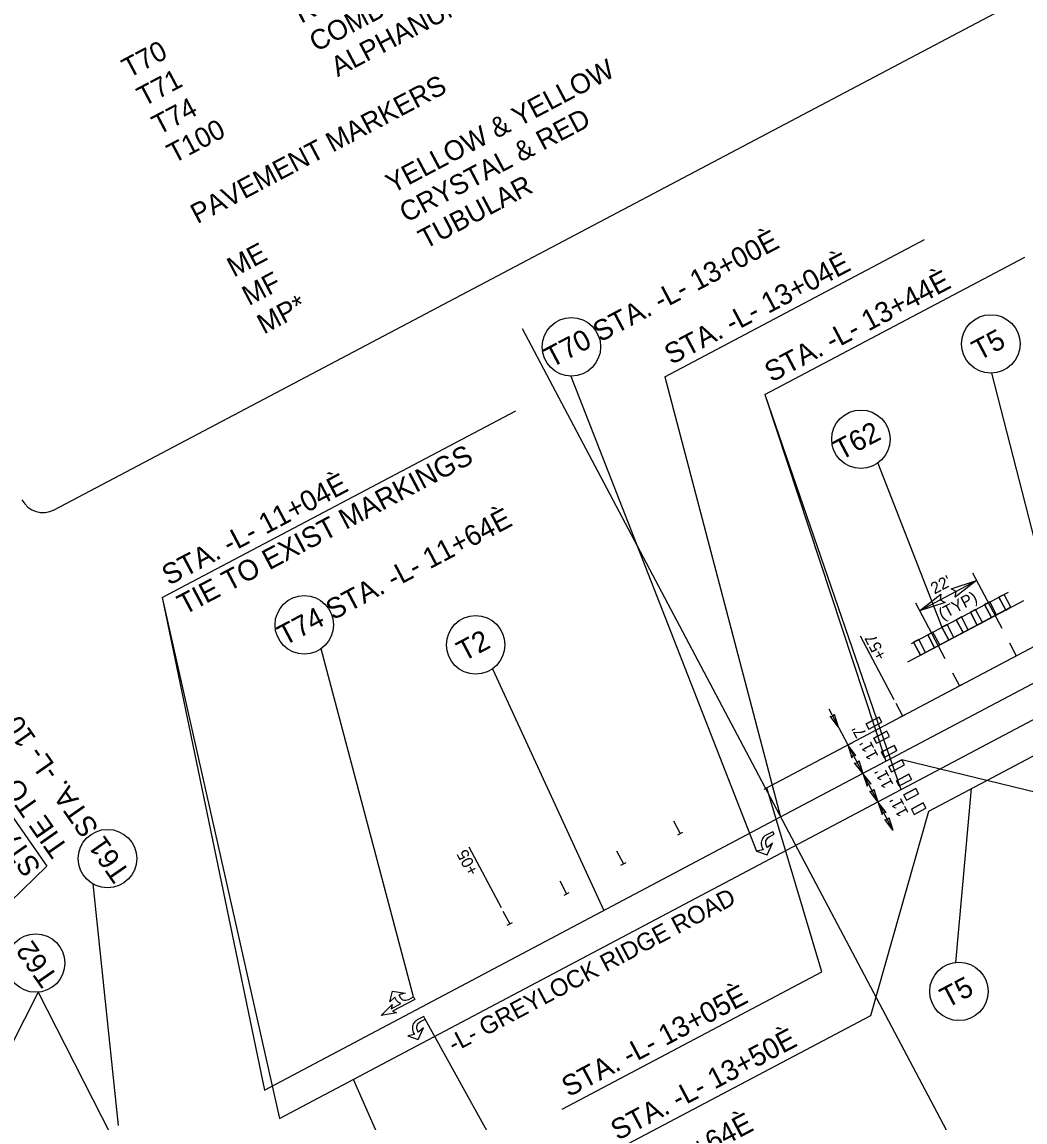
# Model space of a CAD drawing. Extents: x 1487421 to 1489048, y 497792 to 499463.
# Drawn here: x 1487756.3 to 1488099.3, y 498391.7 to 498767.8 of the extents above; entities that cross this region are included whole.
import ezdxf

# ---------------------------------------------------------------- set-up
doc = ezdxf.new("R2010")
doc.units = 0
for name, color, linetype in [('Default', 7, 'Continuous'), ('MARK LEFT TURN ARROW CELL', 7, 'Continuous'), ('MARK STRAIGHT RIGHT ARROW CELL', 7, 'Continuous'), ('Prop Dimension', 7, 'Continuous'), ('Prop Dimension Text', 7, 'Continuous'), ('Prop Horizontal Alignment Direction Label', 7, 'Continuous'), ('Prop Mkg 3ft Min Skp 9ft White', 7, 'Continuous'), ('Prop Mkg Solid Dbl Yel Rpm 80ft', 7, 'Continuous'), ('Prop Mkg Solid White Lane Line', 7, 'Continuous'), ('Scratch_Level_2', 7, 'Continuous'), ('Scratch_Level_3', 7, 'Continuous'), ('Scratch_Level_5', 7, 'Continuous'), ('Scratch_Level_6', 7, 'Continuous'), ('Sheet Title CELL', 7, 'Continuous'), ('Text', 7, 'Continuous')]:
    doc.layers.add(name, color=color, linetype=linetype)

msp = doc.modelspace()

# ---------------------------------------------------------------- linework, layer by layer
at = {"layer": 'MARK LEFT TURN ARROW CELL'}
for points in [[(1488013.55, 498490.11), (1488013.08, 498490.99), (1488010.8, 498489.79), (1488010.39, 498489.54), (1488010.1, 498489.31), (1488009.81, 498489.02), (1488009.6, 498488.71), (1488009.45, 498488.44), (1488009.29, 498488.04), (1488009.22, 498487.71), (1488009.15, 498487.34), (1488009.12, 498486.88), (1488009.16, 498486.54), (1488009.25, 498486.1), (1488009.45, 498485.55), (1488009.82, 498484.84), (1488007.52, 498484.38), (1488011.13, 498483.08), (1488012.98, 498487.07), (1488011.23, 498485.58), (1488010.91, 498486.17), (1488010.76, 498486.51), (1488010.68, 498486.86), (1488010.67, 498487.16), (1488010.69, 498487.56), (1488010.74, 498487.86), (1488010.91, 498488.25), (1488011.16, 498488.59), (1488011.42, 498488.89), (1488011.85, 498489.21)], [(1488013.55, 498490.11), (1488013.08, 498490.99), (1488010.8, 498489.78), (1488010.39, 498489.54), (1488010.1, 498489.31), (1488009.81, 498489.02), (1488009.6, 498488.71), (1488009.45, 498488.44), (1488009.3, 498488.04), (1488009.22, 498487.71), (1488009.15, 498487.34), (1488009.12, 498486.88), (1488009.16, 498486.54), (1488009.25, 498486.1), (1488009.45, 498485.55), (1488009.82, 498484.84), (1488007.53, 498484.38), (1488011.13, 498483.08), (1488012.98, 498487.07), (1488011.23, 498485.58), (1488010.92, 498486.17), (1488010.76, 498486.51), (1488010.68, 498486.86), (1488010.67, 498487.16), (1488010.69, 498487.56), (1488010.74, 498487.86), (1488010.91, 498488.25), (1488011.16, 498488.59), (1488011.42, 498488.89), (1488011.85, 498489.21)], [(1487894.23, 498426.95), (1487893.77, 498427.83), (1487891.48, 498426.63), (1487891.07, 498426.38), (1487890.78, 498426.15), (1487890.49, 498425.86), (1487890.28, 498425.55), (1487890.14, 498425.28), (1487889.98, 498424.88), (1487889.9, 498424.55), (1487889.83, 498424.18), (1487889.81, 498423.72), (1487889.84, 498423.38), (1487889.93, 498422.94), (1487890.13, 498422.39), (1487890.51, 498421.68), (1487888.21, 498421.22), (1487891.82, 498419.92), (1487893.67, 498423.91), (1487891.91, 498422.42), (1487891.6, 498423.01), (1487891.44, 498423.35), (1487891.37, 498423.7), (1487891.35, 498424), (1487891.37, 498424.4), (1487891.43, 498424.7), (1487891.6, 498425.09), (1487891.84, 498425.43), (1487892.11, 498425.73), (1487892.54, 498426.05)], [(1487894.24, 498426.95), (1487893.77, 498427.83), (1487891.48, 498426.62), (1487891.08, 498426.38), (1487890.78, 498426.15), (1487890.49, 498425.86), (1487890.28, 498425.55), (1487890.14, 498425.28), (1487889.98, 498424.88), (1487889.9, 498424.55), (1487889.83, 498424.18), (1487889.81, 498423.72), (1487889.85, 498423.38), (1487889.93, 498422.94), (1487890.13, 498422.39), (1487890.51, 498421.68), (1487888.21, 498421.22), (1487891.82, 498419.92), (1487893.67, 498423.91), (1487891.91, 498422.42), (1487891.6, 498423.01), (1487891.44, 498423.35), (1487891.37, 498423.7), (1487891.35, 498424), (1487891.37, 498424.4), (1487891.43, 498424.7), (1487891.6, 498425.09), (1487891.84, 498425.43), (1487892.11, 498425.73), (1487892.54, 498426.05)]]:
    msp.add_lwpolyline(points, close=True, dxfattribs=at)
at = {"layer": 'MARK STRAIGHT RIGHT ARROW CELL'}
msp.add_lwpolyline([(1487890.69, 498433.66), (1487883.03, 498429.61), (1487884.42, 498429.12), (1487879.18, 498428.15), (1487882.94, 498431.92), (1487882.56, 498430.49), (1487885.9, 498432.26), (1487885.36, 498432.49), (1487885.01, 498432.7), (1487884.66, 498433.03), (1487884.42, 498433.31), (1487884.14, 498433.7), (1487883.78, 498434.44), (1487882.1, 498432.8), (1487883.06, 498436.51), (1487887.4, 498435.78), (1487885.18, 498435.18), (1487885.49, 498434.61), (1487885.69, 498434.28), (1487885.95, 498433.98), (1487886.26, 498433.76), (1487886.59, 498433.56), (1487887.06, 498433.42), (1487887.56, 498433.4), (1487888.05, 498433.47), (1487888.55, 498433.65), (1487890.23, 498434.54)], close=True, dxfattribs=at)
msp.add_lwpolyline([(1487890.69, 498433.66), (1487883.03, 498429.61), (1487884.42, 498429.12), (1487879.18, 498428.15), (1487882.94, 498431.92), (1487882.56, 498430.49), (1487885.9, 498432.26), (1487885.36, 498432.49), (1487885.01, 498432.7), (1487884.66, 498433.03), (1487884.42, 498433.31), (1487884.14, 498433.7), (1487883.78, 498434.44), (1487882.1, 498432.8), (1487883.06, 498436.51), (1487887.4, 498435.78), (1487885.18, 498435.18), (1487885.49, 498434.61), (1487885.69, 498434.28), (1487885.95, 498433.98), (1487886.26, 498433.76), (1487886.59, 498433.56), (1487887.06, 498433.42), (1487887.56, 498433.4), (1487888.05, 498433.47), (1487888.55, 498433.65), (1487890.23, 498434.54)], close=True, dxfattribs=at)
at = {"layer": 'Prop Dimension'}
for p, q in [((1488081.34, 498579.51), (1488091.38, 498560.54)), ((1488063.3, 498566.56), (1488082.74, 498576.86)), ((1488061.89, 498569.22), (1488071.93, 498550.25)), ((1488042.93, 498558.02), (1488054.47, 498536.21)), ((1488032.22, 498533), (1488038.74, 498520.67)), ((1488036.98, 498519.74), (1488040.4, 498521.55)), ((1488038.74, 498520.67), (1488043.89, 498510.95)), ((1488043.89, 498510.95), (1488049.04, 498501.23)), ((1488049.04, 498501.23), (1488054.18, 498491.51)), ((1487909.16, 498485.83), (1487920.13, 498465.1))]:
    msp.add_line(p, q, dxfattribs=at)
for points in [[(1488074.06, 498574.02), (1488082.74, 498576.86), (1488075.49, 498571.21), (1488075.76, 498573.16)], [(1488071.98, 498569.4), (1488063.3, 498566.56), (1488070.55, 498572.21), (1488070.28, 498570.26)], [(1488034.05, 498531.2), (1488035.47, 498526.86), (1488032.64, 498530.48), (1488033.62, 498530.35)], [(1488041.53, 498517.06), (1488038.74, 498520.67), (1488040.15, 498516.3), (1488040.59, 498517.18)], [(1488042.47, 498515.29), (1488043.89, 498510.95), (1488041.07, 498514.57), (1488042.04, 498514.44)], [(1488046.68, 498507.33), (1488043.89, 498510.95), (1488045.3, 498506.58), (1488045.74, 498507.46)], [(1488047.62, 498505.57), (1488049.04, 498501.23), (1488046.21, 498504.85), (1488047.19, 498504.72)], [(1488051.83, 498497.61), (1488049.04, 498501.23), (1488050.45, 498496.85), (1488050.88, 498497.74)], [(1488052.76, 498495.85), (1488054.18, 498491.51), (1488051.36, 498495.13), (1488052.33, 498495)]]:
    msp.add_lwpolyline(points, close=True, dxfattribs=at)
at = {"layer": 'Prop Mkg 3ft Min Skp 9ft White'}
msp.add_line((1488015.76, 498496.06), (1488109.9, 498545.89), dxfattribs=at)
at = {"layer": 'Prop Mkg Solid Dbl Yel Rpm 80ft'}
msp.add_line((1487844.38, 498392.89), (1488115.05, 498536.17), dxfattribs=at)
at = {"layer": 'Prop Mkg Solid White Lane Line'}
for p, q in [((1488094, 498555.58), (1488096.34, 498551.16)), ((1488095.46, 498550.69), (1488097.23, 498551.63)), ((1488074.56, 498545.29), (1488076.9, 498540.87)), ((1488076.01, 498540.4), (1488077.78, 498541.34)), ((1488055.12, 498535), (1488057.45, 498530.58)), ((1488056.57, 498530.11), (1488058.34, 498531.04)), ((1487839.23, 498402.61), (1488015.76, 498496.06)), ((1487979.11, 498494.76), (1487981.45, 498490.34)), ((1487980.56, 498489.87), (1487982.33, 498490.81)), ((1487959.66, 498484.47), (1487962, 498480.05)), ((1487961.12, 498479.58), (1487962.89, 498480.52)), ((1487940.22, 498474.17), (1487942.56, 498469.76)), ((1487941.68, 498469.29), (1487943.44, 498470.22)), ((1487920.78, 498463.88), (1487923.12, 498459.46)), ((1487922.23, 498458.99), (1487924, 498459.93))]:
    msp.add_line(p, q, dxfattribs=at)
at = {"layer": 'Scratch_Level_2'}
msp.add_line((1487927.34, 498663.1), (1488114.48, 498309.57), dxfattribs=at)
at = {"layer": 'Scratch_Level_3'}
for p, q in [((1488045.04, 498527.86), (1488049.45, 498530.2)), ((1488049.45, 498530.2), (1488045.04, 498527.86)), ((1488045.97, 498526.09), (1488045.04, 498527.86)), ((1488045.04, 498527.86), (1488045.97, 498526.09)), ((1488045.97, 498526.09), (1488050.39, 498528.43)), ((1488045.97, 498526.09), (1488050.39, 498528.43)), ((1488050.39, 498528.43), (1488049.45, 498530.2)), ((1488050.39, 498528.43), (1488049.45, 498530.2)), ((1488047.61, 498523), (1488052.03, 498525.33)), ((1488052.03, 498525.33), (1488047.61, 498523)), ((1488048.55, 498521.23), (1488047.61, 498523)), ((1488047.61, 498523), (1488048.55, 498521.23)), ((1488048.55, 498521.23), (1488052.96, 498523.57)), ((1488048.55, 498521.23), (1488052.96, 498523.57)), ((1488052.96, 498523.57), (1488052.03, 498525.34)), ((1488052.96, 498523.57), (1488052.03, 498525.33)), ((1488050.18, 498518.14), (1488054.6, 498520.47)), ((1488054.6, 498520.47), (1488050.18, 498518.14)), ((1488054.6, 498520.47), (1488055.54, 498518.71)), ((1488055.54, 498518.71), (1488054.6, 498520.47)), ((1488050.18, 498518.14), (1488051.12, 498516.37)), ((1488050.18, 498518.14), (1488051.12, 498516.37)), ((1488051.12, 498516.37), (1488055.54, 498518.71)), ((1488051.12, 498516.37), (1488055.54, 498518.71)), ((1488052.76, 498513.27), (1488057.17, 498515.61)), ((1488057.17, 498515.61), (1488052.76, 498513.27)), ((1488058.11, 498513.85), (1488057.17, 498515.61)), ((1488058.11, 498513.84), (1488057.17, 498515.61)), ((1488218.32, 498476.2), (1488057.17, 498515.61)), ((1488053.69, 498511.51), (1488052.76, 498513.27)), ((1488052.76, 498513.27), (1488053.69, 498511.51)), ((1488053.69, 498511.51), (1488058.11, 498513.84)), ((1488053.69, 498511.51), (1488058.11, 498513.84)), ((1488055.33, 498508.41), (1488059.56, 498510.65)), ((1488059.56, 498510.65), (1488055.33, 498508.41)), ((1488056.27, 498506.65), (1488055.33, 498508.41)), ((1488055.33, 498508.41), (1488056.27, 498506.65)), ((1488056.27, 498506.65), (1488060.47, 498508.87)), ((1488056.27, 498506.65), (1488060.47, 498508.87)), ((1488059.56, 498510.65), (1488060.47, 498508.87)), ((1488060.47, 498508.87), (1488059.56, 498510.65)), ((1488057.9, 498503.55), (1488062.05, 498505.75)), ((1488062.05, 498505.75), (1488057.9, 498503.55)), ((1488062.05, 498505.75), (1488062.95, 498503.96)), ((1488062.95, 498503.96), (1488062.05, 498505.75)), ((1488058.84, 498501.78), (1488057.9, 498503.55)), ((1488057.9, 498503.55), (1488058.84, 498501.78)), ((1488058.84, 498501.78), (1488062.95, 498503.96)), ((1488058.84, 498501.78), (1488062.95, 498503.96)), ((1488060.48, 498498.69), (1488064.54, 498500.84)), ((1488064.54, 498500.84), (1488060.48, 498498.69)), ((1488064.54, 498500.84), (1488065.44, 498499.06)), ((1488065.44, 498499.06), (1488064.54, 498500.84)), ((1488060.48, 498498.69), (1488061.41, 498496.92)), ((1488061.41, 498496.92), (1488065.44, 498499.06)), ((1488061.41, 498496.92), (1488065.44, 498499.06))]:
    msp.add_line(p, q, dxfattribs=at)
at = {"layer": 'Scratch_Level_5'}
for p, q in [((1488094, 498555.58), (1488096.34, 498551.16)), ((1488074.56, 498545.29), (1488076.9, 498540.87)), ((1488055.12, 498535), (1488057.45, 498530.58))]:
    msp.add_line(p, q, dxfattribs=at)
at = {"layer": 'Scratch_Level_6'}
for p, q in [((1488010.39, 498640.5), (1488099.23, 498687.41)), ((1488087.84, 498647.78), (1488110.69, 498558.78)), ((1488010.39, 498640.5), (1488051.78, 498515.12)), ((1488010.39, 498640.5), (1488056.92, 498505.4)), ((1488048.97, 498617), (1488070.94, 498560.91)), ((1488060.52, 498555.4), (1488093.68, 498572.95)), ((1488090.38, 498571.2), (1488092.15, 498572.14)), ((1488092.15, 498572.14), (1488090.38, 498571.2)), ((1488094.48, 498567.72), (1488092.15, 498572.14)), ((1488094.48, 498567.72), (1488092.15, 498572.14)), ((1488059.27, 498549.07), (1488098.88, 498570.05)), ((1488085.52, 498568.63), (1488087.28, 498569.57)), ((1488087.29, 498569.56), (1488085.52, 498568.63)), ((1488087.86, 498564.21), (1488085.52, 498568.63)), ((1488085.52, 498568.63), (1488087.86, 498564.21)), ((1488089.62, 498565.15), (1488087.29, 498569.56)), ((1488089.62, 498565.15), (1488087.29, 498569.56)), ((1488092.72, 498566.79), (1488090.38, 498571.2)), ((1488090.38, 498571.2), (1488092.72, 498566.79)), ((1488094.48, 498567.72), (1488063.55, 498551.34)), ((1488077.56, 498564.42), (1488075.8, 498563.48)), ((1488077.56, 498564.42), (1488075.8, 498563.48)), ((1488079.9, 498560), (1488077.56, 498564.42)), ((1488079.9, 498560), (1488077.56, 498564.42)), ((1488080.66, 498566.06), (1488082.42, 498566.99)), ((1488082.43, 498566.99), (1488080.66, 498566.05)), ((1488083, 498561.64), (1488080.66, 498566.05)), ((1488080.66, 498566.05), (1488083, 498561.64)), ((1488084.76, 498562.57), (1488082.43, 498566.99)), ((1488084.76, 498562.57), (1488082.43, 498566.99)), ((1488089.62, 498565.15), (1488087.86, 498564.21)), ((1488087.86, 498564.21), (1488089.62, 498565.15)), ((1488094.48, 498567.72), (1488092.72, 498566.79)), ((1488092.72, 498566.79), (1488094.48, 498567.72)), ((1488070.94, 498560.91), (1488072.7, 498561.84)), ((1488072.7, 498561.84), (1488070.94, 498560.91)), ((1488073.27, 498556.49), (1488070.94, 498560.91)), ((1488070.94, 498560.91), (1488073.27, 498556.49)), ((1488075.04, 498557.43), (1488072.7, 498561.84)), ((1488075.04, 498557.43), (1488072.7, 498561.84)), ((1488078.14, 498559.06), (1488075.8, 498563.48)), ((1488075.8, 498563.48), (1488078.14, 498559.06)), ((1488084.76, 498562.57), (1488083, 498561.64)), ((1488083, 498561.64), (1488084.76, 498562.57)), ((1488067.84, 498559.27), (1488066.07, 498558.33)), ((1488067.84, 498559.27), (1488066.07, 498558.33)), ((1488068.41, 498553.92), (1488066.07, 498558.33)), ((1488066.07, 498558.33), (1488068.41, 498553.92)), ((1488070.18, 498554.85), (1488067.84, 498559.27)), ((1488070.18, 498554.85), (1488067.84, 498559.27)), ((1488073.27, 498556.49), (1488075.04, 498557.43)), ((1488073.27, 498556.49), (1488075.04, 498557.43)), ((1488079.9, 498560), (1488078.14, 498559.06)), ((1488078.14, 498559.06), (1488079.9, 498560)), ((1488010.18, 498505.55), (1488104.75, 498555.61)), ((1488062.98, 498556.7), (1488061.21, 498555.76)), ((1488062.98, 498556.7), (1488061.21, 498555.76)), ((1488063.55, 498551.34), (1488061.21, 498555.76)), ((1488061.21, 498555.76), (1488063.55, 498551.34)), ((1488065.32, 498552.28), (1488062.98, 498556.7)), ((1488065.32, 498552.28), (1488062.98, 498556.7)), ((1488070.18, 498554.85), (1488068.41, 498553.92)), ((1488068.41, 498553.92), (1488070.18, 498554.85)), ((1488065.32, 498552.28), (1488063.55, 498551.34)), ((1488063.55, 498551.34), (1488065.32, 498552.28)), ((1488066.49, 498498.02), (1488120.19, 498526.45)), ((1488029.84, 498443.07), (1488011.07, 498506.02)), ((1488075.63, 498446.33), (1488081.08, 498505.74)), ((1488046.62, 498428.2), (1488066.49, 498498.02)), ((1487941, 498396.16), (1488029.84, 498443.07)), ((1487957.78, 498381.29), (1488046.62, 498428.2))]:
    msp.add_line(p, q, dxfattribs=at)
for centre in [(1488087.65, 498657.77), (1488043.21, 498625.18), (1488076.74, 498436.4)]:
    msp.add_circle(centre, 10, dxfattribs=at)
at = {"layer": 'Sheet Title CELL'}
msp.add_line((1487767.36, 498601.05), (1488152.76, 498804.55), dxfattribs=at)
msp.add_arc((1487763.54, 498608.28), 8.18, 207.8351, 297.8351, dxfattribs=at)
at = {"layer": 'Text'}
for p, q in [((1487976.13, 498646.52), (1488064.97, 498693.43)), ((1487943.97, 498646.76), (1488007.53, 498484.38)), ((1487976.13, 498646.52), (1488015.76, 498496.06)), ((1487804.28, 498571.06), (1487925.18, 498634.9)), ((1487686.51, 498591.29), (1487764.84, 498479.24)), ((1487804.28, 498571.06), (1487839.23, 498402.61)), ((1487804.28, 498571.06), (1487844.38, 498392.89)), ((1487890.23, 498434.54), (1487858.61, 498553.54)), ((1487917.22, 498546.72), (1487955.3, 498464.05)), ((1487764.84, 498479.24), (1487708.26, 498424.53)), ((1487780.49, 498473.16), (1487789.23, 498390.59)), ((1487761.79, 498436.13), (1487741.6, 498396.25)), ((1487761.79, 498436.13), (1487786.53, 498387.54)), ((1487929.6, 498363.11), (1487894.24, 498426.95)), ((1487900.25, 498337.62), (1487869.63, 498406.26))]:
    msp.add_line(p, q, dxfattribs=at)
for centre in [(1487944.19, 498656.76), (1487852.85, 498561.71), (1487911.46, 498554.9), (1487785.54, 498481.79), (1487760.99, 498446.09)]:
    msp.add_circle(centre, 10, dxfattribs=at)

# ---------------------------------------------------------------- texts
at = {"layer": 'Default'}
for s, p in [(' T74                  COMBO RIGHT/STRAIGHT ARROW', (1487800.84, 498727.9)), (' T70                  LEFT TURN ARROW', (1487790.57, 498747.36)), (' T71                  RIGHT TURN ARROW', (1487795.71, 498737.63)), (' T100                 ALPHANUMERIC CHAR.', (1487805.98, 498718.17)), (' ME                   YELLOW & YELLOW', (1487826.53, 498679.25)), ('PAVEMENT MARKERS', (1487816.26, 498698.71)), (' MF                   CRYSTAL & RED', (1487831.67, 498669.52)), (' MP*                  TUBULAR', (1487836.81, 498659.79))]:
    msp.add_text(s, height=6.7709, rotation=27.8351, dxfattribs=at).set_placement(p)
at = {"layer": 'Prop Dimension'}
for s, rotation, p in [("22'", 27.914, (1488068.4, 498572.09)), ('(TYP)', 27.914, (1488071.08, 498563.33)), ("7'", 117.895, (1488045.3, 498524.42)), ("11'", 117.895, (1488049.31, 498516.83)), ("11'", 117.895, (1488054.46, 498507.11)), ("11'", 117.895, (1488059.61, 498497.39))]:
    msp.add_text(s, height=4, rotation=rotation, dxfattribs=at).set_placement(p)
at = {"layer": 'Prop Dimension Text'}
for s, p in [('+57', (1488052.1, 498550.98)), ('+05', (1487912.53, 498477.34))]:
    msp.add_text(s, height=4, rotation=117.895, dxfattribs=at).set_placement(p)
at = {"layer": 'Prop Horizontal Alignment Direction Label'}
msp.add_text('-L- GREYLOCK RIDGE ROAD', height=6, rotation=27.895, dxfattribs=at).set_placement((1487904.03, 498415.38))
at = {"layer": 'Scratch_Level_6'}
for s, p in [('STA. -L- 13+44È', (1488012.64, 498644.5)), ('T5', (1488083.56, 498651.92)), ('T62', (1488036.33, 498617.85)), ('T5', (1488072.65, 498430.54)), ('STA. -L- 13+05È', (1487943.25, 498400.15)), ('STA. -L- 13+50È', (1487960.03, 498385.29))]:
    msp.add_text(s, height=7, rotation=27.835, dxfattribs=at).set_placement(p)
at = {"layer": 'Text'}
for s, rotation, p in [('T70 STA. -L- 13+00È', 27.835, (1487937.41, 498649.49)), ('STA. -L- 13+04È', 27.835, (1487978.38, 498650.52)), ('TIE TO EXIST MARKINGS', 27.835, (1487811.84, 498564.99)), ('STA. -L- 11+04È', 27.835, (1487806.53, 498575.05)), ('T74 STA. -L- 11+64È', 27.835, (1487846.07, 498554.44)), ('TIE TO EXIST MARKINGS', 124.9554, (1487772.41, 498485.32)), ('T2', 27.835, (1487907.36, 498549.05)), ('T61 STA. -L- 10+54È', 124.9556, (1487793.56, 498476.88)), ('STA. -Y1- 136+71È', 124.9554, (1487763.09, 498478.8)), ('T62', 124.9556, (1487768.9, 498441.11)), ('T70 STA. -L- 11+64È', 27.835, (1487928.58, 498347.67))]:
    msp.add_text(s, height=7, rotation=rotation, dxfattribs=at).set_placement(p)

doc.saveas('drawing.dxf')
